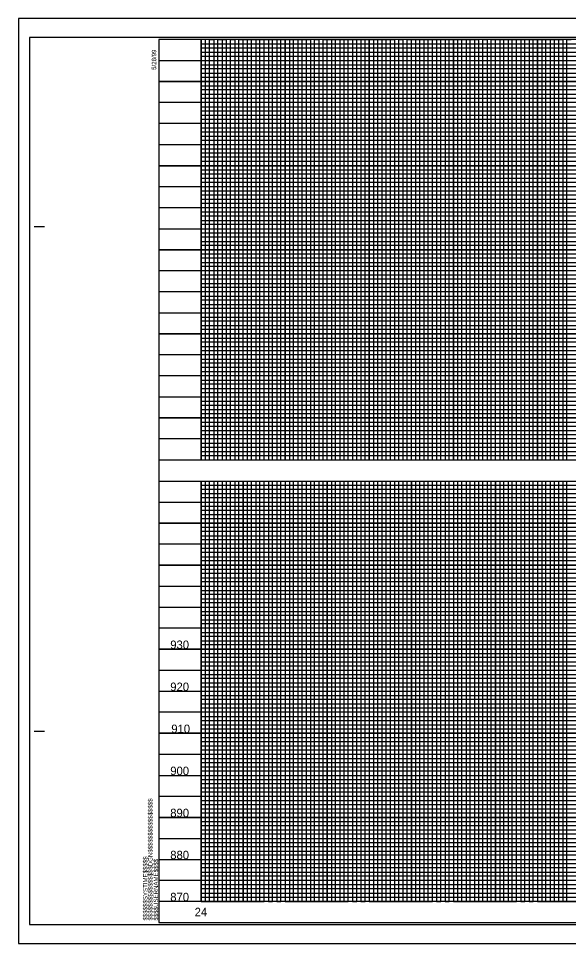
# Model space of a CAD drawing. Extents: x 1648862 to 1650855, y 808691 to 809791.
# Drawn here: x 1648862 to 1649516, y 808691 to 809791 of the extents above; entities that cross this region are included whole.
import ezdxf

# ---------------------------------------------------------------- set-up
doc = ezdxf.new("R2010")
doc.units = 0
for name, color, linetype in [('Exist Vertical Profile Horizontal Axis Label Major', 7, 'Continuous'), ('Exist Vertical Profile Vertical Axis Label', 7, 'Continuous'), ('Sheet Cutting Line CELL', 7, 'Continuous'), ('Sheet DOT Grid CELL', 7, 'Continuous'), ('Sheet Layout Profile Border Port 1', 7, 'Continuous'), ('Sheet Layout Profile Border Port 2', 7, 'Continuous'), ('Sheet Plot Border Inside CELL', 7, 'Continuous'), ('Sheet Plot Border Outside CELL', 7, 'Continuous'), ('Sheet Profile CELL', 7, 'Continuous'), ('Sheet Profile Grid Major CELL', 7, 'Continuous'), ('Sheet Profile Grid Middle CELL', 7, 'Continuous'), ('Sheet Profile Grid Minor CELL', 7, 'Continuous')]:
    doc.layers.add(name, color=color, linetype=linetype)

msp = doc.modelspace()

# ---------------------------------------------------------------- linework, layer by layer
at = {"layer": 'Sheet Cutting Line CELL'}
for p, q in [((1650546.3, 809791), (1648862.3, 809791)), ((1648862.3, 809791), (1648862.3, 808691)), ((1648862.3, 808691), (1650546.3, 808691))]:
    msp.add_line(p, q, dxfattribs=at)
at = {"layer": 'Sheet DOT Grid CELL'}
for p, q in [((1649079.3, 809266), (1649079.3, 809766)), ((1649079.3, 809266), (1649079.3, 809766)), ((1649079.3, 809266), (1649079.3, 809766)), ((1649129.3, 809266), (1649129.3, 809766)), ((1649129.3, 809266), (1649129.3, 809766)), ((1649129.3, 809266), (1649129.3, 809766)), ((1649179.3, 809266), (1649179.3, 809766)), ((1649179.3, 809266), (1649179.3, 809766)), ((1649179.3, 809266), (1649179.3, 809766)), ((1649229.3, 809266), (1649229.3, 809766)), ((1649229.3, 809266), (1649229.3, 809766)), ((1649229.3, 809266), (1649229.3, 809766)), ((1649279.3, 809266), (1649279.3, 809766)), ((1649279.3, 809266), (1649279.3, 809766)), ((1649279.3, 809266), (1649279.3, 809766)), ((1649329.3, 809266), (1649329.3, 809766)), ((1649329.3, 809266), (1649329.3, 809766)), ((1649329.3, 809266), (1649329.3, 809766)), ((1649379.3, 809266), (1649379.3, 809766)), ((1649379.3, 809266), (1649379.3, 809766)), ((1649379.3, 809266), (1649379.3, 809766)), ((1649429.3, 809266), (1649429.3, 809766)), ((1649429.3, 809266), (1649429.3, 809766)), ((1649429.3, 809266), (1649429.3, 809766)), ((1649479.3, 809266), (1649479.3, 809766)), ((1649479.3, 809266), (1649479.3, 809766)), ((1649479.3, 809266), (1649479.3, 809766)), ((1650329.2, 809716), (1649029.3, 809716)), ((1650329.2, 809716), (1649029.3, 809716)), ((1650329.2, 809716), (1649029.3, 809716)), ((1650329.2, 809666), (1649029.3, 809666)), ((1650329.2, 809666), (1649029.3, 809666)), ((1650329.2, 809666), (1649029.3, 809666)), ((1650329.3, 809616), (1649029.3, 809616)), ((1650329.3, 809616), (1649029.3, 809616)), ((1650329.3, 809616), (1649029.3, 809616)), ((1650529.3, 809566), (1649029.3, 809566)), ((1650529.3, 809566), (1649029.3, 809566)), ((1650529.3, 809566), (1649029.3, 809566)), ((1650529.3, 809516), (1649029.3, 809516)), ((1650529.3, 809516), (1649029.3, 809516)), ((1650529.3, 809516), (1649029.3, 809516)), ((1650529.3, 809466), (1649029.3, 809466)), ((1650529.3, 809466), (1649029.3, 809466)), ((1650529.3, 809466), (1649029.3, 809466)), ((1650529.3, 809416), (1649029.3, 809416)), ((1650529.3, 809416), (1649029.3, 809416)), ((1650529.3, 809416), (1649029.3, 809416)), ((1650529.3, 809366), (1649029.3, 809366)), ((1650529.3, 809366), (1649029.3, 809366)), ((1650529.3, 809366), (1649029.3, 809366)), ((1650529.3, 809316), (1649029.3, 809316)), ((1650529.3, 809316), (1649029.3, 809316)), ((1650529.3, 809316), (1649029.3, 809316)), ((1649029.3, 809241), (1650529.2, 809241)), ((1649079.3, 809241), (1649079.3, 808741)), ((1649129.3, 809241), (1649129.3, 808741)), ((1649179.3, 809241), (1649179.3, 808741)), ((1649229.3, 809241), (1649229.3, 808741)), ((1649279.3, 809241), (1649279.3, 808741)), ((1649329.3, 809241), (1649329.3, 808741)), ((1649379.3, 809241), (1649379.3, 808741)), ((1649429.3, 809241), (1649429.3, 808741)), ((1649479.3, 809241), (1649479.3, 808741)), ((1649029.3, 809191), (1650529.2, 809191)), ((1649029.3, 809141), (1650529.2, 809141)), ((1649029.3, 809091), (1650529.2, 809091)), ((1649029.3, 809041), (1650529.2, 809041)), ((1649029.3, 808991), (1650529.2, 808991)), ((1649029.3, 808941), (1650529.2, 808941)), ((1649029.3, 808891), (1650529.2, 808891)), ((1649029.3, 808841), (1650529.2, 808841)), ((1649029.3, 808791), (1650529.2, 808791))]:
    msp.add_line(p, q, dxfattribs=at)
at = {"layer": 'Sheet Layout Profile Border Port 1'}
msp.add_lwpolyline([(1649079.3, 809605), (1649079.3, 809266), (1650479.3, 809266), (1650479.3, 809605)], dxfattribs=at)
at = {"layer": 'Sheet Layout Profile Border Port 2'}
msp.add_lwpolyline([(1649079.3, 809241), (1650479.3, 809241), (1650479.3, 808741), (1649079.3, 808741)], close=True, dxfattribs=at)
at = {"layer": 'Sheet Plot Border Inside CELL'}
msp.add_lwpolyline([(1648875.3, 808713.5), (1650541.8, 808713.5), (1650541.8, 809768.6), (1648875.3, 809768.6)], close=True, dxfattribs=at)
at = {"layer": 'Sheet Plot Border Outside CELL'}
msp.add_lwpolyline([(1648862.3, 808691), (1650546.3, 808691), (1650546.3, 809791), (1648862.3, 809791)], close=True, dxfattribs=at)
at = {"layer": 'Sheet Profile CELL'}
for p, q in [((1648880.8, 809543.5), (1648893.3, 809543.5)), ((1649029.3, 809266), (1650529.3, 809266)), ((1649029.3, 809241), (1650529.3, 809241)), ((1648880.8, 808943.5), (1648893.3, 808943.5)), ((1650529.3, 808741), (1649029.3, 808741)), ((1649029.3, 808716), (1650529.3, 808716)), ((1649029.3, 808716), (1649029.3, 808716)), ((1649029.3, 808716), (1649029.3, 808716)), ((1649029.3, 808716), (1649029.3, 808716)), ((1649029.3, 808716), (1649029.3, 808716)), ((1649029.3, 808716), (1649029.3, 808716)), ((1649029.3, 808716), (1649029.3, 808716)), ((1649029.3, 808716), (1649029.3, 808716))]:
    msp.add_line(p, q, dxfattribs=at)
msp.add_lwpolyline([(1650529.3, 809766), (1649029.3, 809766), (1649029.3, 808716), (1650529.3, 808716)], close=True, dxfattribs=at)
msp.add_lwpolyline([(1649066.8, 808716), (1649066.8, 808716)], dxfattribs=at)
at = {"layer": 'Sheet Profile Grid Major CELL'}
msp.add_line((1649029.3, 808741), (1649029.3, 808741), dxfattribs=at)
for points in [[(1649079.3, 809766), (1649079.3, 809266), (1649129.3, 809266), (1649129.3, 809766), (1649179.3, 809766), (1649179.3, 809266), (1649229.3, 809266), (1649229.3, 809766), (1649279.3, 809766), (1649279.3, 809266), (1649329.3, 809266), (1649329.3, 809766), (1649379.3, 809766), (1649379.3, 809266), (1649429.3, 809266), (1649429.3, 809766), (1649479.3, 809766), (1649479.3, 809266), (1649529.3, 809266)], [(1649029.3, 809716), (1650329.3, 809716)], [(1650329.3, 809666), (1649029.3, 809666), (1649029.3, 809616), (1650329.3, 809616)], [(1650529.3, 809566), (1649029.3, 809566), (1649029.3, 809516), (1650529.3, 809516)], [(1650529.3, 809466), (1649029.3, 809466), (1649029.3, 809416), (1650529.3, 809416)], [(1650529.3, 809366), (1649029.3, 809366), (1649029.3, 809366), (1649029.3, 809316), (1650529.3, 809316)], [(1649079.3, 809241), (1649079.3, 808741), (1649129.3, 808741), (1649129.3, 809241), (1649179.3, 809241), (1649179.3, 808741), (1649229.3, 808741), (1649229.3, 809241), (1649279.3, 809241), (1649279.3, 808741), (1649329.3, 808741), (1649329.3, 809241), (1649379.3, 809241), (1649379.3, 808741), (1649429.3, 808741), (1649429.3, 809241), (1649479.3, 809241), (1649479.3, 808741), (1649529.3, 808741)], [(1650529.3, 809191), (1649029.3, 809191)], [(1650529.3, 809141), (1649029.3, 809141), (1649029.3, 809091), (1650529.3, 809091)], [(1650529.3, 809041), (1649029.3, 809041), (1649029.3, 808991), (1650529.3, 808991)], [(1650529.3, 808941), (1649029.3, 808941), (1649029.3, 808891), (1650529.3, 808891)], [(1650529.3, 808841), (1649029.3, 808841), (1649029.3, 808841), (1649029.3, 808791), (1650529.3, 808791)], [(1650529.3, 808741), (1649029.3, 808741)]]:
    msp.add_lwpolyline(points, dxfattribs=at)
at = {"layer": 'Sheet Profile Grid Middle CELL'}
msp.add_line((1649029.3, 809741), (1650179.3, 809741), dxfattribs=at)
for points in [[(1649104.3, 809766), (1649104.3, 809266), (1649154.3, 809266), (1649154.3, 809766), (1649204.3, 809766), (1649204.3, 809266), (1649254.3, 809266), (1649254.3, 809766), (1649304.3, 809766), (1649304.3, 809266), (1649354.3, 809266), (1649354.3, 809766), (1649404.3, 809766), (1649404.3, 809266), (1649454.3, 809266), (1649454.3, 809766), (1649504.3, 809766), (1649504.3, 809266), (1649554.3, 809266)], [(1650329.3, 809691), (1649029.3, 809691), (1649029.3, 809641), (1650329.3, 809641)], [(1650529.3, 809591), (1649029.3, 809591), (1649029.3, 809541), (1650354.3, 809541)], [(1650529.3, 809491), (1649029.3, 809491), (1649029.3, 809441), (1650529.3, 809441)], [(1650529.3, 809391), (1649029.3, 809391), (1649029.3, 809341), (1650529.3, 809341)], [(1650529.3, 809291), (1649029.3, 809291)], [(1649054.3, 809241), (1649104.3, 809241), (1649104.3, 808741), (1649154.3, 808741), (1649154.3, 809241), (1649204.3, 809241), (1649204.3, 808741), (1649254.3, 808741), (1649254.3, 809241), (1649304.3, 809241), (1649304.3, 808741), (1649354.3, 808741), (1649354.3, 809241), (1649404.3, 809241), (1649404.3, 808741), (1649454.3, 808741), (1649454.3, 809241), (1649504.3, 809241), (1649504.3, 808741), (1649554.3, 808741)], [(1649029.3, 809216), (1650529.3, 809216)], [(1650529.3, 809166), (1649029.3, 809166), (1649029.3, 809116), (1650529.3, 809116)], [(1650529.3, 809066), (1649029.3, 809066), (1649029.3, 809016), (1650529.3, 809016)], [(1650529.3, 808966), (1649029.3, 808966), (1649029.3, 808916), (1650529.3, 808916)], [(1650529.3, 808866), (1649029.3, 808866), (1649029.3, 808816), (1650529.3, 808816)], [(1650529.3, 808766), (1649029.3, 808766)]]:
    msp.add_lwpolyline(points, dxfattribs=at)
at = {"layer": 'Sheet Profile Grid Minor CELL'}
for p, q in [((1649079.3, 809761), (1650037.4, 809761)), ((1649079.3, 809761), (1650179.3, 809761)), ((1649079.3, 809756), (1649079.3, 809756)), ((1649079.3, 809756), (1649079.3, 809756)), ((1649079.3, 809756), (1649079.3, 809756)), ((1649079.3, 809756), (1649079.3, 809756)), ((1650179.3, 809756), (1649079.3, 809755.7)), ((1650037.4, 809755.9), (1649079.3, 809755.7)), ((1649079.3, 809751), (1650179.3, 809751)), ((1650329.2, 809631), (1649079.3, 809631)), ((1650329.3, 809626), (1649079.3, 809626)), ((1650329.3, 809621), (1649079.3, 809621)), ((1649079.3, 809611), (1650329.3, 809611)), ((1650329.3, 809606), (1649079.3, 809606)), ((1649079.3, 809601), (1650479.3, 809601)), ((1650479.3, 809581), (1649079.3, 809581)), ((1649079.3, 809576), (1650479.3, 809576)), ((1650479.3, 809556), (1649079.3, 809556)), ((1649079.3, 809551), (1650479.3, 809551)), ((1650479.3, 809531), (1649079.3, 809531)), ((1649079.3, 809526), (1650479.3, 809526)), ((1650479.3, 809521), (1649079.3, 809521)), ((1649079.3, 809511), (1650479.3, 809511)), ((1650479.3, 809506), (1649079.3, 809506)), ((1649079.3, 809501), (1650479.3, 809501)), ((1650479.3, 809496), (1649079.3, 809496)), ((1649079.3, 809486), (1650479.3, 809486)), ((1650479.3, 809481), (1649079.3, 809481)), ((1649079.3, 809476), (1650479.3, 809476)), ((1650479.3, 809471), (1649079.3, 809471)), ((1649079.3, 809461), (1650479.3, 809461)), ((1650479.3, 809456), (1649079.3, 809456)), ((1649079.3, 809451), (1650479.3, 809451)), ((1650479.3, 809446), (1649079.3, 809446)), ((1649079.3, 809436), (1650479.3, 809436)), ((1650479.3, 809431), (1649079.3, 809431)), ((1649079.3, 809426), (1650479.3, 809426)), ((1650479.3, 809421), (1649079.3, 809421)), ((1649079.3, 809411), (1650479.3, 809411)), ((1650479.3, 809406), (1649079.3, 809406)), ((1649079.3, 809401), (1650479.3, 809401)), ((1650479.3, 809396), (1649079.3, 809396)), ((1649079.3, 809386), (1650479.3, 809386)), ((1650479.3, 809381), (1649079.3, 809381)), ((1650479.3, 809376), (1649079.3, 809376)), ((1650479.3, 809371), (1649079.3, 809371)), ((1649079.3, 809361), (1650479.3, 809361)), ((1650479.3, 809356), (1649079.3, 809356)), ((1649079.3, 809351), (1650479.3, 809351)), ((1650479.3, 809346), (1649079.3, 809346)), ((1649079.3, 809336), (1650479.3, 809336)), ((1650479.3, 809331), (1649079.3, 809331)), ((1649079.3, 809326), (1650479.3, 809326)), ((1650479.3, 809321), (1649079.3, 809321)), ((1649079.3, 809311), (1650479.3, 809311)), ((1650479.3, 809306), (1649079.3, 809306)), ((1649079.3, 809301), (1650479.3, 809301)), ((1650479.3, 809296), (1649079.3, 809296)), ((1649079.3, 809286), (1650479.3, 809286)), ((1650479.3, 809281), (1649079.3, 809281)), ((1649079.3, 809276), (1650479.3, 809276)), ((1649079.3, 809236), (1650479.3, 809236)), ((1650479.3, 809231), (1649079.3, 809231)), ((1649079.3, 809226), (1650479.3, 809226)), ((1650479.3, 809221), (1649079.3, 809221)), ((1649079.3, 809211), (1650479.3, 809211)), ((1650479.3, 809206), (1649079.3, 809206)), ((1649079.3, 809201), (1650479.3, 809201)), ((1650479.3, 809196), (1649079.3, 809196)), ((1649079.3, 809186), (1650479.3, 809186)), ((1650479.3, 809181), (1649079.3, 809181)), ((1649079.3, 809176), (1650479.3, 809176)), ((1650479.3, 809171), (1649079.3, 809171)), ((1649079.3, 809161), (1650479.3, 809161)), ((1650479.3, 809156), (1649079.3, 809156)), ((1649079.3, 809151), (1650479.3, 809151)), ((1650479.3, 809146), (1649079.3, 809146)), ((1649079.3, 809136), (1650479.3, 809136)), ((1650479.3, 809131), (1649079.3, 809131)), ((1649079.3, 809126), (1650479.3, 809126)), ((1650479.3, 809121), (1649079.3, 809121)), ((1649079.3, 809111), (1650479.3, 809111)), ((1650479.3, 809106), (1649079.3, 809106)), ((1649079.3, 809101), (1650479.3, 809101)), ((1650479.3, 809096), (1649079.3, 809096)), ((1649079.3, 809086), (1650479.3, 809086)), ((1650479.3, 809081), (1649079.3, 809081)), ((1649079.3, 809076), (1650479.3, 809076)), ((1650479.3, 809071), (1649079.3, 809071)), ((1649079.3, 809061), (1650479.3, 809061)), ((1650479.3, 809056), (1649079.3, 809056)), ((1649079.3, 809051), (1650479.3, 809051)), ((1650479.3, 809046), (1649079.3, 809046.2)), ((1649079.3, 809036), (1650479.3, 809036)), ((1650479.3, 809031), (1649079.3, 809031)), ((1649079.3, 809026), (1650479.3, 809026)), ((1650479.3, 809021), (1649079.3, 809021)), ((1649079.3, 809011), (1650479.3, 809011)), ((1650479.3, 809006), (1649079.3, 809006)), ((1649079.3, 809001), (1650479.3, 809001)), ((1650479.3, 808996), (1649079.3, 808996)), ((1649079.3, 808986), (1650479.3, 808986)), ((1650479.3, 808981), (1649079.3, 808981)), ((1649079.3, 808976), (1650479.3, 808976)), ((1650479.3, 808971), (1649079.3, 808971)), ((1649079.3, 808961), (1650479.3, 808961)), ((1650479.3, 808956), (1649079.3, 808956)), ((1649079.3, 808951), (1650479.3, 808951)), ((1650479.3, 808946), (1649079.3, 808946)), ((1649079.3, 808936), (1650479.3, 808936)), ((1650479.3, 808931), (1649079.3, 808931)), ((1649079.3, 808926), (1650479.3, 808926)), ((1650479.3, 808921), (1649079.3, 808921)), ((1649079.3, 808911), (1650479.3, 808911)), ((1650479.3, 808906), (1649079.3, 808906)), ((1649079.3, 808901), (1650479.3, 808901)), ((1650479.3, 808896), (1649079.3, 808896)), ((1649079.3, 808886), (1650479.3, 808886)), ((1650479.3, 808881), (1649079.3, 808881)), ((1649079.3, 808876), (1650479.3, 808876)), ((1650479.3, 808871), (1649079.3, 808871)), ((1649079.3, 808861), (1650479.3, 808861)), ((1650479.3, 808856), (1649079.3, 808856)), ((1649079.3, 808851), (1650479.3, 808851)), ((1650479.3, 808846), (1649079.3, 808846)), ((1649079.3, 808836), (1650479.3, 808836)), ((1650479.3, 808831), (1649079.3, 808831)), ((1649079.3, 808826), (1650479.3, 808826)), ((1650479.3, 808821), (1649079.3, 808821)), ((1649079.3, 808811), (1650479.3, 808811)), ((1650479.3, 808806), (1649079.3, 808806)), ((1649079.3, 808801), (1650479.3, 808801)), ((1650479.3, 808796), (1649079.3, 808796)), ((1649079.3, 808786), (1650479.3, 808786)), ((1650479.3, 808781), (1649079.3, 808781)), ((1649079.3, 808776), (1650479.3, 808776)), ((1650479.3, 808771), (1649079.3, 808771)), ((1649079.3, 808761), (1650479.3, 808761)), ((1650479.3, 808756), (1649079.3, 808756)), ((1649079.3, 808751), (1650479.3, 808751)), ((1649079.3, 808746), (1650479.3, 808746))]:
    msp.add_line(p, q, dxfattribs=at)
for points in [[(1649084.3, 809766), (1649084.3, 809266), (1649089.3, 809266), (1649089.3, 809766), (1649094.3, 809766), (1649094.3, 809266), (1649099.3, 809266), (1649099.3, 809766), (1649109.3, 809766), (1649109.3, 809266), (1649114.3, 809266), (1649114.3, 809766), (1649119.3, 809766), (1649119.3, 809266), (1649124.3, 809266), (1649134.3, 809266), (1649139.3, 809266), (1649139.3, 809766), (1649144.3, 809766), (1649144.3, 809266), (1649149.3, 809266), (1649149.3, 809766), (1649159.3, 809766), (1649159.3, 809266), (1649164.3, 809266), (1649164.3, 809766), (1649169.3, 809766), (1649169.3, 809266), (1649174.3, 809266), (1649174.3, 809766), (1649184.3, 809766), (1649184.3, 809266), (1649189.3, 809266), (1649189.3, 809766), (1649194.3, 809766), (1649194.3, 809266), (1649199.3, 809266), (1649199.3, 809766), (1649209.3, 809766), (1649209.3, 809266), (1649214.3, 809266), (1649214.3, 809766), (1649219.3, 809766), (1649219.3, 809266), (1649224.3, 809266), (1649224.3, 809766), (1649234.3, 809766), (1649234.3, 809266), (1649239.3, 809266), (1649239.3, 809766), (1649244.3, 809766), (1649244.3, 809266), (1649249.3, 809266), (1649249.3, 809766), (1649259.3, 809766), (1649259.3, 809266), (1649264.3, 809266), (1649264.3, 809766), (1649269.3, 809766), (1649269.3, 809266), (1649274.3, 809266), (1649274.3, 809766), (1649284.3, 809766), (1649284.3, 809266), (1649289.3, 809266), (1649289.3, 809766), (1649294.3, 809766), (1649294.3, 809266)], [(1649124.3, 809266), (1649124.3, 809766), (1649134.3, 809766), (1649134.3, 809266)], [(1649294.3, 809266), (1649299.3, 809266), (1649299.3, 809766), (1649309.3, 809766), (1649309.3, 809266), (1649314.3, 809266), (1649314.3, 809766), (1649319.3, 809766), (1649319.3, 809266), (1649324.3, 809266), (1649324.3, 809766), (1649334.3, 809766), (1649334.3, 809266), (1649339.3, 809266), (1649339.3, 809766), (1649344.3, 809766), (1649344.3, 809266), (1649349.3, 809266), (1649349.3, 809766), (1649359.3, 809766), (1649359.3, 809266), (1649364.3, 809266), (1649364.3, 809766), (1649369.3, 809766), (1649369.3, 809266), (1649374.3, 809266), (1649374.3, 809766), (1649384.3, 809766), (1649384.3, 809266), (1649389.3, 809266), (1649389.3, 809766), (1649394.3, 809766), (1649394.3, 809266), (1649399.3, 809266), (1649399.3, 809766), (1649409.3, 809766), (1649409.3, 809266), (1649414.3, 809266), (1649414.3, 809766), (1649419.3, 809766), (1649419.3, 809266), (1649424.3, 809266), (1649424.3, 809766), (1649434.3, 809766), (1649434.3, 809266), (1649439.3, 809266), (1649439.3, 809766), (1649444.3, 809766), (1649444.3, 809266), (1649449.3, 809266), (1649449.3, 809766), (1649459.3, 809766), (1649459.3, 809266), (1649464.3, 809266), (1649464.3, 809766), (1649469.3, 809766), (1649469.3, 809266), (1649474.3, 809266), (1649474.3, 809766), (1649484.3, 809766), (1649484.3, 809266), (1649489.3, 809266), (1649489.3, 809766), (1649494.3, 809766), (1649494.3, 809266), (1649499.3, 809266), (1649499.3, 809766), (1649509.3, 809766), (1649509.3, 809266), (1649514.3, 809266), (1649514.3, 809766), (1649519.3, 809766)], [(1650179.3, 809746), (1649079.3, 809746), (1649079.3, 809736), (1650329.3, 809736)], [(1650329.2, 809731), (1649079.3, 809731), (1649079.3, 809726), (1650329.3, 809726)], [(1650329.3, 809721), (1649079.3, 809721), (1649079.3, 809711), (1650329.3, 809711)], [(1650329.3, 809706), (1649079.3, 809706), (1649079.3, 809701), (1650329.3, 809701)], [(1650329.3, 809696), (1649079.3, 809696), (1649079.3, 809686), (1650329.3, 809686)], [(1650329.3, 809681), (1649079.3, 809681), (1649079.3, 809676), (1650329.3, 809676)], [(1650329.3, 809671), (1649079.3, 809671), (1649079.3, 809661), (1650329.3, 809661)], [(1650329.3, 809655.9), (1649079.4, 809655.9), (1649079.4, 809651), (1650329.3, 809651)], [(1650329.3, 809646), (1649079.3, 809646), (1649079.3, 809636), (1650329.3, 809636)], [(1650479.3, 809596), (1649079.3, 809596), (1649079.3, 809586), (1650479.3, 809586)], [(1650479.3, 809571), (1649079.3, 809571), (1649079.3, 809561), (1650479.3, 809561)], [(1650479.3, 809546), (1649079.3, 809546), (1649079.3, 809536), (1650479.3, 809536)], [(1650479.3, 809271), (1649079.3, 809271)], [(1649079.3, 809241), (1649084.3, 809241), (1649084.3, 808741), (1649089.3, 808741), (1649089.3, 809241), (1649094.3, 809241), (1649094.3, 808741), (1649099.3, 808741), (1649099.3, 809241), (1649109.3, 809241), (1649109.3, 808741), (1649114.3, 808741), (1649114.3, 809241), (1649119.3, 809241), (1649119.3, 808741), (1649124.3, 808741), (1649134.3, 808741), (1649139.3, 808741), (1649139.3, 809241), (1649144.3, 809241), (1649144.3, 808741), (1649149.3, 808741), (1649149.3, 809241), (1649159.3, 809241), (1649159.3, 808741), (1649164.3, 808741), (1649164.3, 809241), (1649169.3, 809241), (1649169.3, 808741), (1649174.3, 808741), (1649174.3, 809241), (1649184.3, 809241), (1649184.3, 808741), (1649189.3, 808741), (1649189.3, 809241), (1649194.3, 809241), (1649194.3, 808741), (1649199.3, 808741), (1649199.3, 809241), (1649209.3, 809241), (1649209.3, 808741), (1649214.3, 808741), (1649214.3, 809241), (1649219.3, 809241), (1649219.3, 808741), (1649224.3, 808741), (1649224.3, 809241), (1649234.3, 809241), (1649234.3, 808741), (1649239.3, 808741), (1649239.3, 809241), (1649244.3, 809241), (1649244.3, 808741), (1649249.3, 808741), (1649249.3, 809241), (1649259.3, 809241), (1649259.3, 808741), (1649264.3, 808741), (1649264.3, 809241), (1649269.3, 809241), (1649269.3, 808741), (1649274.3, 808741), (1649274.3, 809241), (1649284.3, 809241), (1649284.3, 808741), (1649289.3, 808741), (1649289.3, 809241), (1649294.3, 809241), (1649294.3, 808741)], [(1649124.3, 808741), (1649124.3, 809241), (1649134.3, 809241), (1649134.3, 808741)], [(1649294.3, 808741), (1649299.3, 808741), (1649299.3, 809241), (1649309.3, 809241), (1649309.3, 808741), (1649314.3, 808741), (1649314.3, 809241), (1649319.3, 809241), (1649319.3, 808741), (1649324.3, 808741), (1649324.3, 809241), (1649334.3, 809241), (1649334.3, 808741), (1649339.3, 808741), (1649339.3, 809241), (1649344.3, 809241), (1649344.3, 808741), (1649349.3, 808741), (1649349.3, 809241), (1649359.3, 809241), (1649359.3, 808741), (1649364.3, 808741), (1649364.3, 809241), (1649369.3, 809241), (1649369.3, 808741), (1649374.3, 808741), (1649374.3, 809241), (1649384.3, 809241), (1649384.3, 808741), (1649389.3, 808741), (1649389.3, 809241), (1649394.3, 809241), (1649394.3, 808741), (1649399.3, 808741), (1649399.3, 809241), (1649409.3, 809241), (1649409.3, 808741), (1649414.3, 808741), (1649414.3, 809241), (1649419.3, 809241), (1649419.3, 808741), (1649424.3, 808741), (1649424.3, 809241), (1649434.3, 809241), (1649434.3, 808741), (1649439.3, 808741), (1649439.3, 809241), (1649444.3, 809241), (1649444.3, 808741), (1649449.3, 808741), (1649449.3, 809241), (1649459.3, 809241), (1649459.3, 808741), (1649464.3, 808741), (1649464.3, 809241), (1649469.3, 809241), (1649469.3, 808741), (1649474.3, 808741), (1649474.3, 809241), (1649484.3, 809241), (1649484.3, 808741), (1649489.3, 808741), (1649489.3, 809241), (1649494.3, 809241), (1649494.3, 808741), (1649499.3, 808741), (1649499.3, 809241), (1649509.3, 809241), (1649509.3, 808741), (1649514.3, 808741), (1649514.3, 809241), (1649519.3, 809241)]]:
    msp.add_lwpolyline(points, dxfattribs=at)

# ---------------------------------------------------------------- texts
at = {"layer": 'Exist Vertical Profile Horizontal Axis Label Major'}
msp.add_text('24', height=10, dxfattribs=at).set_placement((1649071.7, 808723.5))
at = {"layer": 'Exist Vertical Profile Vertical Axis Label'}
for s, p in [('930', (1649042.7, 809041.3)), ('920', (1649042.7, 808991.3)), ('910', (1649043.9, 808941.3)), ('900', (1649042.7, 808891.3)), ('890', (1649042.7, 808841.3)), ('880', (1649042.7, 808791.3)), ('870', (1649042.7, 808741.3))]:
    msp.add_text(s, height=10, dxfattribs=at).set_placement(p)
at = {"layer": 'Sheet Profile CELL'}
for s, p in [('5/28/99', (1649026, 809729.9)), ('$$$$$$$$$$$$$$$$DGN$$$$$$$$$$$$$$$$', (1649021.6, 808718.4)), ('$$$$$$SYSTIME$$$$$', (1649015.6, 808718.4)), ('$$$$USERNAME$$$$', (1649028.2, 808718.4))]:
    msp.add_text(s, height=5.25, rotation=90, dxfattribs=at).set_placement(p)

doc.saveas('drawing.dxf')
